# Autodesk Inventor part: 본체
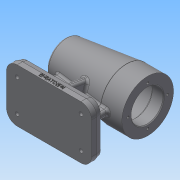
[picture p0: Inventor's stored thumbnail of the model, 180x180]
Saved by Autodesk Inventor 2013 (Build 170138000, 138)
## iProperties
Created: 2017-01
Part Number: 본체
Material: 일반
Document SubType Name: Modeling
Designer: Administrator
Density: 1 g/cm^3
Author: Administrator
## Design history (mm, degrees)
sketch "스케치1"
  geometry: L1 (-56, 0)-(56, 0); L2 (-52.27, 24.144)-(28, 34); L3 (28, 34)-(56, 34); L4 (56, 34)-(56, 0); A1 r 80 centre (24, 0) between (-52.27, 24.144) and (-56, 0); 1 further point
  constraints: 8 end point, 2 point on circle, 1 centre point, 1 horizontal, 1 midpoint, 1 parallel, 1 perpendicular, 1 point on line
  dimensions: "d0" = 112 distance of L1.start L1.end; "d2" = 56 distance of point (0, 0) L1.start; "d3" = 28 distance of L2.end L3.end; "d4" = 7 deg angle of L3 L2; "d5" = 80 radius of A1; "d6" = 68 diameter of L3 L1
revolve "회전1" sketch "스케치1" stored, may be unused: angle "d7" = 90 deg
sketch "스케치2"
  geometry: C1 r 34 at (0, 0) reference
hole "구멍1" sketch "스케치2" at (0, 0) diameter "d8" = 42; stored, may be unused: countersink angle "d12" = 90 deg, drill point angle "d14" = 0 deg; dims "d9" = 6, "d10" = 42, "d11" = 15, "d13" = 15
sketch "스케치3"
  geometry: C1 r 21 at (0, 0) reference
hole "구멍2" sketch "스케치3" at (0, 0) diameter "d15" = 42; stored, may be unused: countersink angle "d19" = 90 deg, drill point angle "d21" = 0 deg; dims "d16" = 6, "d17" = 48, "d18" = 54, "d20" = 66
sketch "스케치4"
  geometry: C1 r 21 at (0, 0) reference
hole "구멍3" sketch "스케치4" at (0, 0) diameter "d22" = 32; stored, may be unused: countersink angle "d26" = 90 deg, drill point angle "d28" = 0 deg; dims "d23" = 6, "d24" = 35, "d25" = 18, "d27" = 22
sketch "스케치5"
  geometry: C1 r 16 at (0, 0) reference
hole "구멍4" sketch "스케치5" at (0, 0) diameter "d29" = 21; stored, may be unused: countersink angle "d33" = 90 deg, drill point angle "d35" = 0 deg; dims "d30" = 6, "d31" = 35, "d32" = 18, "d34" = 3
fillet "모깎기1" dims "d36" = 3
fillet "모깎기2" dims "d37" = 3
sketch "스케치9"
  geometry: C1 r 21 at (0, 0) reference; C2 r 24 at (0, 0) reference; 1 further point
  constraints: 1 vertical alignment
  dimensions: "d38" = 26 distance of C2.centre point (0, 26)
hole "구멍5" sketch "스케치9" at (0, 26) diameter "d39" = 3.242; stored, may be unused: countersink angle "d43" = 90 deg, drill point angle "d45" = 118 deg; dims "d40" = 8, "d41" = 35, "d42" = 18, "d44" = 11
node "작업 평면1"
sketch "스케치10"
  geometry: L1 (56, 35)-(-56, 35); L2 (-56, 35)-(-56, -35); L3 (-56, -35)-(56, -35); L4 (56, -35)-(56, 35); L5 (56, 35)-(-56, -35); L6 (-56, 35)-(56, -35); 4 further points
  constraints: 12 end point, 4 midpoint, 2 parallel, 1 horizontal, 1 horizontal alignment, 1 perpendicular, 1 vertical alignment
  dimensions: "d50" = 112 distance of L1.start L1.end; "d52" = 70 distance of L1.end L2.end
extrude "돌출1" join sketch "스케치10" distance "d53" = 7; taper "d54" = 0 deg
fillet "모깎기12" dims "d119" = 14
sketch "스케치23"
  geometry: L1 (42, 35)-(-42, 35) reference; L2 (-56, 21)-(-56, -21) reference; L3 (-42, -35)-(42, -35) reference; L4 (56, -21)-(56, 21) reference; A1 r 14 centre (42, 21) between (56, 21) and (42, 35) reference; A2 r 14 centre (-42, 21) between (-42, 35) and (-56, 21) reference; A3 r 14 centre (-42, -21) between (-56, -21) and (-42, -35) reference; A4 r 14 centre (42, -21) between (42, -35) and (56, -21) reference; 1 further point
extrude "돌출5" join sketch "스케치23" distance "d120" = 7; taper "d121" = -15 deg
sketch "스케치24"
  geometry: L1 (42, -33.124)-(-42, -33.124) reference; L2 (-38, 4)-(38, 4); L3 (38, 4)-(38, -4); L4 (38, -4)-(-38, -4); L5 (-38, -4)-(-38, 4); L6 (-56, 21)-(-56, -21) reference; L7 (56, -21)-(56, 21) reference; L8 (42, 35)-(-42, 35) reference; 2 further points
  constraints: 8 end point, 3 parallel, 1 horizontal alignment, 1 midpoint, 1 perpendicular
  dimensions: "d122" = 18 distance between parallel lines of L5 L6; "d123" = 18 distance between parallel lines of L7 L3; "d124" = 31 distance between parallel lines of L8 L2
extrude "돌출6" join sketch "스케치24" stored distance "d125" = 7; taper "d126" = 0 deg
node "작업 평면2"
sketch "스케치27" dims "d130" = 10
  geometry: L1 (-39.113, 26)-(-36.226, 21); L2 (-36.226, 21)-(-39.113, 16); L3 (-39.113, 16)-(-44.887, 16); L4 (-44.887, 16)-(-47.774, 21); L5 (-47.774, 21)-(-44.887, 26); L6 (-44.887, 26)-(-39.113, 26); L7 (-39.113, -16)-(-36.226, -21); L8 (-36.226, -21)-(-39.113, -26); L9 (-39.113, -26)-(-44.887, -26); L10 (-44.887, -26)-(-47.774, -21); L11 (-47.774, -21)-(-44.887, -16); L12 (-44.887, -16)-(-39.113, -16); L13 (44.887, 26)-(47.774, 21); L14 (47.774, 21)-(44.887, 16); L15 (44.887, 16)-(39.113, 16); L16 (39.113, 16)-(36.226, 21); L17 (36.226, 21)-(39.113, 26); L18 (39.113, 26)-(44.887, 26); L19 (44.887, -16)-(47.774, -21); L20 (47.774, -21)-(44.887, -26); L21 (44.887, -26)-(39.113, -26); L22 (39.113, -26)-(36.226, -21); L23 (36.226, -21)-(39.113, -16); L24 (39.113, -16)-(44.887, -16); A1 r 12.124 centre (42, 21) between (54.124, 21) and (42, 33.124) reference; A2 r 12.124 centre (-42, 21) between (-42, 33.124) and (-54.124, 21) reference; A3 r 12.124 centre (-42, -21) between (-54.124, -21) and (-42, -33.124) reference; A4 r 12.124 centre (42, -21) between (42, -33.124) and (54.124, -21) reference; 17 further points
  constraints: 48 end point, 11 coincident, 8 vertical alignment, 4 midpoint, 60 other
  dimensions: "d127" = 42 distance of point (-42, -21) point (-42, 21); "d129" = 84 distance of point (42, -21) point (-42, -21)
extrude "돌출7" cut sketch "스케치27" distance "d131" = 4; taper "d132" = 0 deg
sketch "스케치28"
  geometry: L1 (-44.887, 26)-(-39.113, 26) reference; 4 further points
  constraints: 1 horizontal alignment, 1 midpoint, 1 vertical alignment
hole "구멍7" sketch "스케치28" at (-42, 21) diameter "d133" = 5; stored, may be unused: countersink angle "d137" = 90 deg, drill point angle "d139" = 118 deg; dims "d134" = 8, "d135" = 35, "d136" = 18, "d138" = 11
fillet "모깎기5" dims "d106" = 3
fillet "모깎기6" dims "d107" = 0.3
fillet "모깎기10" dims "d113" = 3
sketch "스케치22"
  geometry: L1 (0, 0)-(84, 0); L2 (98, 0)-(98, 7); L3 (84, 7)-(84, 0) reference; L4 (0, 7)-(84, 7) reference; L5 (0, 0)-(0, 7) reference; L6 (0, 0)-(84, 0) reference; 2 further points
  constraints: 4 end point, 1 other
  dimensions: "d115" = 4 distance from line of L1 point (42, 4); "d116" = 56 distance from line of L2 point (42, 4)
feature "엠보싱1" sketch "스케치22" dims "d0" = 112, "d2" = 56, "d3" = 28, "d4" = 7 deg, "d5" = 80, "d6" = 68, "d117" = 0.5, "d118" = 0
sketch "스케치29"
  geometry: L1 (-60, 23)-(-37.773, 19.081); L2 (-60, -23)-(-38.09, -19.137); L3 (-60, -33.124)-(-67, -35) reference; L4 (-67, -35)-(-74, -35) reference; L5 (-74, -35)-(-74, 35) reference; L6 (-74, 35)-(-68.423, 35) reference; L7 (-68.423, 35)-(-68.423, 35.5) reference; L8 (-68.423, 35.5)-(-68.092, 35.5) reference; L9 (-68.092, 35.5)-(-68.092, 35) reference; L10 (-68.092, 35)-(-67, 35) reference; L11 (-67, 35)-(-60, 33.124) reference; L12 (-60, 33.124)-(-60, 4) reference; L13 (-60, 4)-(-30.299, 4) reference; L14 (-30.299, -4)-(-60, -4) reference; L15 (-60, -4)-(-60, -33.124) reference; C1 r 24 at (0, 0) reference; A1 r 30.562 centre (0, 0) between (-30.299, -4) and (-30.299, 4) reference; 1 further point
  constraints: 4 end point, 2 point on line
  dimensions: "d146" = 100 deg angle of L12 L1; "d147" = 100 deg angle of L15 L2; "d148" = 12 distance from line of L1.start L6; "d149" = 12 distance from line of L2.start L4
  node "절단 모서리 투영6"
feature "리브3" dims "d150" = 1, "d151" = 8, "d152" = 0, "d153" = 0, "d154" = 1, "d155" = 1
feature "리브4" dims "d156" = 1, "d157" = 8, "d158" = 0, "d159" = 0, "d160" = 1, "d161" = 1
fillet "모깎기13" dims "d162" = 3
fillet "모깎기14" dims "d163" = 3
fillet "모깎기15" dims "d164" = 3
chamfer "모따기1" distance "d165" = 1; stored, may be unused: second distance "d166" = 2, angle "d167" = 45 deg
fillet "모깎기16" dims "d168" = 1
node "솔리드1"
pattern_circular "원형 패턴1" dims angle "d47" = 360 deg
pattern_linear "직사각형 패턴2" dims "d142" = 42, "d145" = 84
other parameters: "d49" = -74
